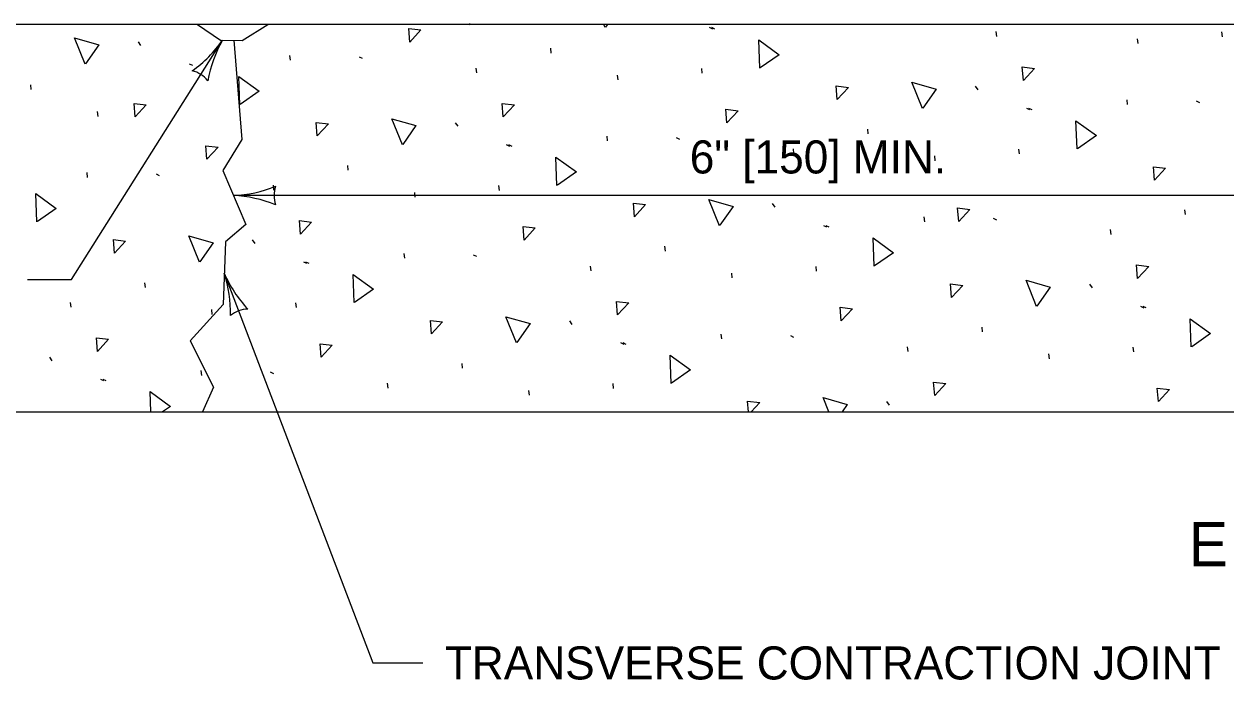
# Model space of a CAD drawing. Extents: x 49991.4 to 50021, y 49987.6 to 50011.4.
# Drawn here: x 50007.688 to 50009.87, y 49992.096 to 49993.286 of the extents above; entities that cross this region are included whole.
import ezdxf

# ---------------------------------------------------------------- set-up
doc = ezdxf.new("R2010")
doc.units = 0
for name, color, linetype in [('Level 1', 7, 'Continuous'), ('Level 2', 7, 'Continuous'), ('Level 20', 7, 'Continuous'), ('Level 3', 7, 'Continuous'), ('Level 4', 7, 'Continuous')]:
    doc.layers.add(name, color=color, linetype=linetype)

msp = doc.modelspace()

# ---------------------------------------------------------------- linework, layer by layer
at = {"layer": 'Level 1'}
msp.add_line((50011.4513, 49993.2857), (50004.6259, 49993.2857), dxfattribs=at)
for points in [[(50008.0687, 49993.257), (50008.0837, 49993.0767), (50008.0492, 49993.0206), (50008.0909, 49992.9228), (50008.0536, 49992.8915), (50008.0493, 49992.7774), (50007.9899, 49992.7114), (50008.0319, 49992.6278), (50008.0123, 49992.5827)], [(50001.9803, 49992.5827), (50004.606, 49992.5827), (50014.3713, 49992.5827)]]:
    msp.add_lwpolyline(points, dxfattribs=at)
at = {"layer": 'Level 20'}
msp.add_lwpolyline([(50008.0028, 49993.2857), (50008.045, 49993.257), (50008.0842, 49993.2563), (50008.1304, 49993.2857)], dxfattribs=at)
at = {"layer": 'Level 3'}
for p, q in [((50007.6956, 49993.2857), (50007.6957, 49993.2858)), ((50008.4956, 49993.2857), (50008.4981, 49993.2872)), ((50009.7956, 49993.2857), (50009.7962, 49993.2861)), ((50010.0672, 49992.9753), (50008.0685, 49992.9753)), ((50007.6945, 49992.8231), (50007.7745, 49992.8231)), ((50008.0514, 49992.8345), (50008.3216, 49992.1273)), ((50008.3216, 49992.1273), (50008.4121, 49992.1273))]:
    msp.add_line(p, q, dxfattribs=at)
msp.add_lwpolyline([(50007.7745, 49992.8231), (50008.0482, 49993.2569)], dxfattribs=at)
for centre, radius, start, end in [((50007.8653, 49993.3832), 0.2223, 305.2071, 325.3906), ((50008.2512, 49993.1425), 0.233, 150.5784, 169.8282), ((50007.9798, 49993.1485), 0.0548, 39.8899, 75.6122), ((50008.057, 49993.208), 0.233, 272.8273, 292.0772), ((50008.1967, 49992.9753), 0.0548, 162.1388, 197.8612), ((50008.0593, 49992.7531), 0.2223, 67.456, 87.6395), ((50007.8406, 49992.7637), 0.2223, 358.3635, 18.547), ((50008.2647, 49992.9282), 0.233, 203.7348, 222.9847), ((50008.0972, 49992.7147), 0.0548, 93.0463, 128.7687)]:
    msp.add_arc(centre, radius, start, end, dxfattribs=at)
at = {"layer": 'Level 4'}
for p, q in [((50008.932, 49993.2805), (50008.9377, 49993.2776)), ((50008.9361, 49993.2805), (50008.9418, 49993.2776)), ((50009.4542, 49993.264), (50009.4533, 49993.2727)), ((50009.8637, 49993.2634), (50009.8628, 49993.2721)), ((50007.895, 49993.2539), (50007.8997, 49993.2474)), ((50009.7108, 49993.2511), (50009.7099, 49993.2598)), ((50008.1717, 49993.2209), (50008.1708, 49993.2296)), ((50008.6452, 49993.2338), (50008.6442, 49993.2425)), ((50007.9878, 49993.2143), (50007.9936, 49993.2115)), ((50008.2962, 49993.2272), (50008.302, 49993.2243)), ((50008.5101, 49993.1978), (50008.5091, 49993.2065)), ((50008.9195, 49993.1973), (50008.9186, 49993.206)), ((50008.7666, 49993.185), (50008.7657, 49993.1937)), ((50007.701, 49993.1677), (50007.7001, 49993.1764)), ((50009.4149, 49993.1735), (50009.4197, 49993.167)), ((50009.6917, 49993.1405), (50009.6907, 49993.1492)), ((50009.8162, 49993.1468), (50009.8219, 49993.1439)), ((50007.8225, 49993.1189), (50007.8215, 49993.1276)), ((50009.5078, 49993.1339), (50009.5135, 49993.1311)), ((50009.5119, 49993.1339), (50009.5176, 49993.1311)), ((50008.4708, 49993.1074), (50008.4755, 49993.1009)), ((50008.7475, 49993.0743), (50008.7466, 49993.083)), ((50008.872, 49993.0806), (50008.8778, 49993.0778)), ((50009.2209, 49993.0873), (50009.22, 49993.0959)), ((50008.5636, 49993.0678), (50008.5693, 49993.0649)), ((50008.5677, 49993.0678), (50008.5734, 49993.065)), ((50009.0858, 49993.0513), (50009.0849, 49993.06)), ((50009.4953, 49993.0507), (50009.4944, 49993.0594)), ((50009.3424, 49993.0384), (50009.3415, 49993.0471)), ((50007.8033, 49993.0082), (50007.8024, 49993.0169)), ((50007.9278, 49993.0145), (50007.9336, 49993.0117)), ((50008.2768, 49993.0211), (50008.2758, 49993.0298)), ((50008.1417, 49992.9852), (50008.1407, 49992.9939)), ((50008.5511, 49992.9846), (50008.5502, 49992.9933)), ((50008.3983, 49992.9723), (50008.3973, 49992.981)), ((50009.0466, 49992.9608), (50009.0513, 49992.9543)), ((50009.7967, 49992.9407), (50009.7958, 49992.9494)), ((50009.3233, 49992.9278), (50009.3223, 49992.9365)), ((50009.4478, 49992.9341), (50009.4536, 49992.9312)), ((50009.1394, 49992.9212), (50009.1451, 49992.9184)), ((50009.1435, 49992.9212), (50009.1492, 49992.9184)), ((50009.6616, 49992.9047), (50009.6607, 49992.9134)), ((50008.1024, 49992.8947), (50008.1071, 49992.8882)), ((50008.8526, 49992.8746), (50008.8516, 49992.8833)), ((50008.3791, 49992.8617), (50008.3782, 49992.8704)), ((50008.5036, 49992.8679), (50008.5094, 49992.8651)), ((50008.1952, 49992.8551), (50008.201, 49992.8523)), ((50008.1993, 49992.8551), (50008.2051, 49992.8523)), ((50008.7175, 49992.8386), (50008.7165, 49992.8473)), ((50009.1269, 49992.838), (50009.126, 49992.8467)), ((50007.9084, 49992.8084), (50007.9075, 49992.8171)), ((50008.974, 49992.8258), (50008.9731, 49992.8345)), ((50009.6223, 49992.8143), (50009.6271, 49992.8078)), ((50007.7733, 49992.7725), (50007.7724, 49992.7812)), ((50008.1828, 49992.7719), (50008.1818, 49992.7806)), ((50009.7152, 49992.7747), (50009.7209, 49992.7718)), ((50009.7193, 49992.7747), (50009.725, 49992.7719)), ((50008.0299, 49992.7596), (50008.0289, 49992.7683)), ((50008.6782, 49992.7481), (50008.6829, 49992.7416)), ((50009.4284, 49992.728), (50009.4274, 49992.7367)), ((50008.771, 49992.7085), (50008.7768, 49992.7057)), ((50008.7751, 49992.7086), (50008.7808, 49992.7057)), ((50008.9549, 49992.7151), (50008.954, 49992.7238)), ((50009.0794, 49992.7214), (50009.0852, 49992.7185)), ((50009.2933, 49992.6921), (50009.2923, 49992.7008)), ((50009.5498, 49992.6792), (50009.5489, 49992.6879)), ((50009.7027, 49992.6915), (50009.7018, 49992.7002)), ((50007.734, 49992.682), (50007.7388, 49992.6755)), ((50008.4842, 49992.6619), (50008.4833, 49992.6706)), ((50007.8268, 49992.6424), (50007.8326, 49992.6396)), ((50007.8309, 49992.6424), (50007.8367, 49992.6396)), ((50008.0107, 49992.649), (50008.0098, 49992.6577)), ((50008.1352, 49992.6552), (50008.141, 49992.6524)), ((50008.3491, 49992.6259), (50008.3482, 49992.6346)), ((50008.6057, 49992.6131), (50008.6047, 49992.6218)), ((50008.7585, 49992.6253), (50008.7576, 49992.634)), ((50009.254, 49992.6016), (50009.2587, 49992.5951))]:
    msp.add_line(p, q, dxfattribs=at)
for points in [[(50008.3885, 49993.2538), (50008.3866, 49993.2784), (50008.4087, 49993.2757), (50008.3885, 49993.2538)], [(50008.7433, 49993.2799), (50008.7409, 49993.2857)], [(50008.7475, 49993.2857), (50008.7439, 49993.2805)], [(50007.7991, 49993.2137), (50007.7798, 49993.2612), (50007.8238, 49993.2487), (50007.7997, 49993.2144)], [(50009.024, 49993.2063), (50009.0221, 49993.2575), (50009.0592, 49993.2307), (50009.0248, 49993.2068)], [(50009.5024, 49993.1841), (50009.5005, 49993.2087), (50009.5226, 49993.206), (50009.5024, 49993.1841)], [(50008.0798, 49993.1402), (50008.078, 49993.1914), (50008.115, 49993.1646), (50008.0806, 49993.1406)], [(50009.1646, 49993.1496), (50009.1628, 49993.1742), (50009.1848, 49993.1715), (50009.1646, 49993.1496)], [(50009.3191, 49993.1333), (50009.2998, 49993.1808), (50009.3438, 49993.1682), (50009.3197, 49993.134)], [(50007.8898, 49993.118), (50007.8879, 49993.1425), (50007.91, 49993.1399), (50007.8898, 49993.118)], [(50008.5582, 49993.118), (50008.5563, 49993.1425), (50008.5784, 49993.1399), (50008.5582, 49993.118)], [(50008.9643, 49993.1072), (50008.9624, 49993.1318), (50008.9845, 49993.1291), (50008.9643, 49993.1072)], [(50008.2205, 49993.0835), (50008.2186, 49993.108), (50008.2406, 49993.1054), (50008.2205, 49993.0835)], [(50008.3749, 49993.0672), (50008.3556, 49993.1147), (50008.3996, 49993.1021), (50008.3755, 49993.0679)], [(50009.5998, 49993.0598), (50009.5979, 49993.111), (50009.635, 49993.0842), (50009.6006, 49993.0602)], [(50008.0201, 49993.0411), (50008.0183, 49993.0657), (50008.0403, 49993.063), (50008.0201, 49993.0411)], [(50008.6556, 49992.9936), (50008.6538, 49993.0448), (50008.6908, 49993.018), (50008.6564, 49992.9941)], [(50009.7404, 49993.0031), (50009.7386, 49993.0276), (50009.7606, 49993.025), (50009.7404, 49993.0031)], [(50007.7115, 49992.9275), (50007.7096, 49992.9787), (50007.7466, 49992.9519), (50007.7122, 49992.9279)], [(50008.9507, 49992.9206), (50008.9314, 49992.9681), (50008.9754, 49992.9556), (50008.9513, 49992.9213)], [(50008.7963, 49992.9369), (50008.7944, 49992.9615), (50008.8164, 49992.9588), (50008.7963, 49992.9369)], [(50009.385, 49992.9283), (50009.3831, 49992.9528), (50009.4051, 49992.9502), (50009.385, 49992.9283)], [(50008.1898, 49992.9053), (50008.188, 49992.9299), (50008.21, 49992.9272), (50008.1898, 49992.9053)], [(50008.0065, 49992.8545), (50007.9873, 49992.902), (50008.0312, 49992.8894), (50008.0071, 49992.8552)], [(50008.5959, 49992.8946), (50008.5941, 49992.9191), (50008.6161, 49992.9165), (50008.5959, 49992.8946)], [(50007.8521, 49992.8708), (50007.8502, 49992.8953), (50007.8722, 49992.8927), (50007.8521, 49992.8708)], [(50009.2314, 49992.8471), (50009.2296, 49992.8983), (50009.2666, 49992.8715), (50009.2322, 49992.8475)], [(50009.7098, 49992.8249), (50009.7079, 49992.8494), (50009.73, 49992.8468), (50009.7098, 49992.8249)], [(50008.2873, 49992.781), (50008.2854, 49992.8322), (50008.3224, 49992.8053), (50008.288, 49992.7814)], [(50009.372, 49992.7904), (50009.3702, 49992.8149), (50009.3922, 49992.8123), (50009.372, 49992.7904)], [(50009.5265, 49992.7741), (50009.5072, 49992.8215), (50009.5512, 49992.809), (50009.5271, 49992.7747)], [(50008.7656, 49992.7587), (50008.7637, 49992.7833), (50008.7858, 49992.7806), (50008.7656, 49992.7587)], [(50009.1717, 49992.748), (50009.1698, 49992.7726), (50009.1919, 49992.7699), (50009.1717, 49992.748)], [(50008.4279, 49992.7242), (50008.426, 49992.7488), (50008.448, 49992.7461), (50008.4279, 49992.7242)], [(50008.5823, 49992.7079), (50008.563, 49992.7554), (50008.607, 49992.7429), (50008.5829, 49992.7086)], [(50009.8072, 49992.7005), (50009.8053, 49992.7517), (50009.8424, 49992.7249), (50009.808, 49992.701)], [(50007.8214, 49992.6926), (50007.8196, 49992.7172), (50007.8416, 49992.7145), (50007.8214, 49992.6926)], [(50008.2275, 49992.6819), (50008.2257, 49992.7064), (50008.2477, 49992.7038), (50008.2275, 49992.6819)], [(50008.863, 49992.6344), (50008.8612, 49992.6856), (50008.8982, 49992.6588), (50008.8638, 49992.6348)], [(50007.9183, 49992.5827), (50007.917, 49992.6195), (50007.954, 49992.5927), (50007.9397, 49992.5827)], [(50009.3414, 49992.6122), (50009.3395, 49992.6367), (50009.3616, 49992.6341), (50009.3414, 49992.6122)], [(50009.7475, 49992.6015), (50009.7456, 49992.626), (50009.7677, 49992.6234), (50009.7475, 49992.6015)], [(50009.0033, 49992.5827), (50009.0018, 49992.6022), (50009.0238, 49992.5996), (50009.0083, 49992.5827)], [(50009.1495, 49992.5827), (50009.1388, 49992.6089), (50009.1828, 49992.5963), (50009.1732, 49992.5827)]]:
    msp.add_lwpolyline(points, dxfattribs=at)

# ---------------------------------------------------------------- texts
at = {"layer": 'Level 2'}
for s, height, p in [('6" [150] MIN.', 0.06, (50008.8967, 49993.0153)), ('E', 0.08, (50009.8026, 49992.3027)), ('TRANSVERSE CONTRACTION JOINT  ', 0.06, (50008.4521, 49992.0973))]:
    msp.add_text(s, height=height, dxfattribs=at).set_placement(p)

doc.saveas('drawing.dxf')
